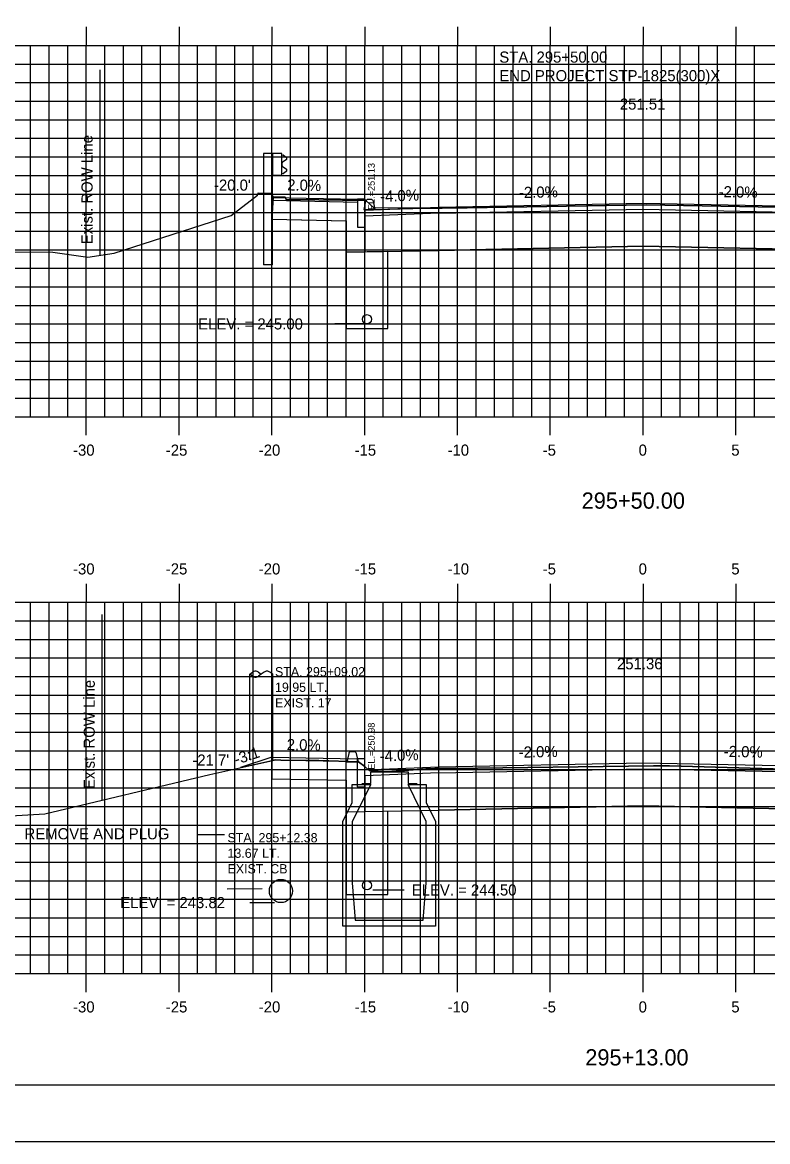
# Model space of a CAD drawing. Extents: x 859575 to 859745, y 366268 to 366378.
# Drawn here: x 859624.4 to 859664.5, y 366268.2 to 366328.5 of the extents above; entities that cross this region are included whole.
import ezdxf

# ---------------------------------------------------------------- set-up
doc = ezdxf.new("R2010")
doc.units = 0
for name, color, linetype in [('ANNOTATION', 7, 'Continuous'), ('BORDER', 7, 'Continuous'), ('D_Curb_Type_1_Lt', 7, 'Continuous'), ('D_Drainage_Culvert', 7, 'Continuous'), ('D_Roadway_Centerline_Text', 7, 'Continuous'), ('D_Roadway_Edge_Shoulder', 7, 'Continuous'), ('D_Roadway_FinishedGrade', 7, 'Continuous'), ('D_Roadway_Sidewalks_Paved', 7, 'Continuous'), ('D_Roadway_SubGrade', 7, 'Continuous'), ('D_Text_Monospaced', 7, 'Continuous'), ('D_Text_Standard', 7, 'Continuous'), ('E_ROW_Line', 7, 'Continuous'), ('H_V ANNOTATION', 7, 'Continuous'), ('JUNK COM EXC', 7, 'Continuous'), ('JUNK FILL', 7, 'Continuous'), ('junk strct exc', 7, 'Continuous'), ('MAJOR', 7, 'Continuous'), ('MINOR', 7, 'Continuous'), ('PDRAIN', 7, 'Continuous'), ('PLOT BOUNDARY', 7, 'Continuous'), ('S_Curb_Type_3', 7, 'Continuous'), ('S_Drainage_CB', 7, 'Continuous'), ('S_Guardrail_Beam', 7, 'Continuous'), ('S_Roadway_Centerline', 7, 'Continuous'), ('S_Utilities_Pole_Power', 7, 'Continuous')]:
    doc.layers.add(name, color=color, linetype=linetype)

msp = doc.modelspace()

# ---------------------------------------------------------------- linework, layer by layer
at = {"layer": 'ANNOTATION'}
for p, q in [((859633.835, 366284.72), (859635.248, 366284.72)), ((859637.266, 366281.799), (859635.393, 366281.786))]:
    msp.add_line(p, q, dxfattribs=at)
at = {"layer": 'BORDER'}
msp.add_line((859582.797, 366271.236), (859742.797, 366271.236), dxfattribs=at)
at = {"layer": 'D_Curb_Type_1_Lt'}
for points in [[(859642.408, 366318.954), (859642.408, 366317.454), (859642.824, 366317.454), (859642.824, 366318.954)], [(859642.385, 366288.799), (859642.385, 366287.299), (859642.801, 366287.299), (859642.801, 366288.799)]]:
    msp.add_lwpolyline(points, close=True, dxfattribs=at)
at = {"layer": 'D_Drainage_Culvert'}
msp.add_circle((859638.286, 366281.681), 0.625, dxfattribs=at)
at = {"layer": 'D_Roadway_Edge_Shoulder'}
for points in [[(859642.824, 366318.371), (859646.797, 366318.53), (859657.797, 366318.75), (859668.797, 366318.53), (859671.791, 366318.41)], [(859642.797, 366288.215), (859646.797, 366288.375), (859657.797, 366288.595), (859668.797, 366288.375), (859672.789, 366288.216)]]:
    msp.add_lwpolyline(points, dxfattribs=at)
at = {"layer": 'D_Roadway_FinishedGrade'}
msp.add_lwpolyline([(859637.796, 366288.891), (859636.109, 366288.328)], dxfattribs=at)
at = {"layer": 'D_Roadway_Sidewalks_Paved'}
for points in [[(859637.819, 366319.045), (859642.408, 366318.954), (859642.408, 366318.787), (859637.819, 366318.879)], [(859637.796, 366288.891), (859642.385, 366288.799), (859642.385, 366288.632), (859637.796, 366288.724)]]:
    msp.add_lwpolyline(points, close=True, dxfattribs=at)
at = {"layer": 'D_Roadway_SubGrade'}
msp.add_line((859637.819, 366318.879), (859637.819, 366317.878), dxfattribs=at)
for points in [[(859637.819, 366317.878), (859641.801, 366317.798), (859641.797, 366316.097), (859642.797, 366316.117)], [(859668.239, 366316.208), (859657.797, 366316.417), (859646.797, 366316.197), (859646.797, 366318.197), (859657.797, 366318.417), (859668.239, 366318.208)], [(859637.796, 366288.724), (859637.796, 366287.724), (859641.801, 366287.644), (859641.797, 366285.942), (859642.797, 366285.962)]]:
    msp.add_lwpolyline(points, dxfattribs=at)
for points in [[(859646.797, 366318.197), (859642.797, 366318.037), (859642.797, 366316.117), (859646.797, 366316.197)], [(859646.797, 366288.042), (859642.797, 366287.882), (859642.797, 366285.962), (859646.797, 366286.042)], [(859646.797, 366286.042), (859646.797, 366288.042), (859657.797, 366288.262), (859668.797, 366288.042), (859668.797, 366286.042), (859657.797, 366286.262)]]:
    msp.add_lwpolyline(points, close=True, dxfattribs=at)
at = {"layer": 'D_Text_Standard'}
for points in [[(859642.922, 366312.237), (859641.873, 366312.237), (859641.193, 366312.237)], [(859643.244, 366281.736), (859644.925, 366281.736)], [(859636.606, 366281.056), (859637.933, 366281.056)]]:
    msp.add_lwpolyline(points, dxfattribs=at)
at = {"layer": 'E_ROW_Line'}
for p, q in [((859628.54, 366315.931), (859628.54, 366325.931)), ((859628.656, 366286.572), (859628.656, 366296.572))]:
    msp.add_line(p, q, dxfattribs=at)
at = {"layer": 'JUNK COM EXC'}
for points in [[(859667.018, 366318.498), (859657.962, 366318.648), (859648.31, 366318.491), (859646.971, 366318.475), (859646.082, 366318.477), (859643.288, 366318.487), (859642.868, 366318.878), (859640.33, 366318.917), (859638.572, 366318.935), (859638.513, 366319.072), (859637.86, 366319.085), (859637.796, 366317.878), (859641.801, 366317.798), (859641.797, 366316.097), (859646.797, 366316.197), (859657.797, 366316.417), (859668.239, 366316.208)], [(859668.536, 366288.155), (859659.214, 366288.419), (859658.795, 366288.425), (859658.355, 366288.418), (859647.53, 366288.285), (859646.925, 366288.287), (859646.584, 366288.284), (859646.095, 366288.27), (859644.021, 366288.11), (859643.042, 366288.179), (859642.804, 366288.381), (859642.458, 366288.643), (859640.331, 366288.713), (859638.286, 366288.739), (859638.012, 366288.757), (859637.796, 366288.708)], [(859637.796, 366288.708), (859637.796, 366287.724), (859641.801, 366287.644), (859641.797, 366285.942), (859646.797, 366286.042), (859657.797, 366286.262), (859668.797, 366286.042)]]:
    msp.add_lwpolyline(points, dxfattribs=at)
at = {"layer": 'JUNK FILL'}
msp.add_lwpolyline([(859637.797, 366288.708), (859637.797, 366288.891), (859637.796, 366288.891), (859636.109, 366288.328)], close=True, dxfattribs=at)
at = {"layer": 'junk strct exc'}
msp.add_lwpolyline([(859641.797, 366316.097), (859641.797, 366311.986), (859644.047, 366311.986), (859644.047, 366316.142)], close=True, dxfattribs=at)
at = {"layer": 'MAJOR'}
for p, q in [((859627.797, 366328.238), (859627.797, 366327.236)), ((859632.797, 366328.238), (859632.797, 366327.236)), ((859637.797, 366328.238), (859637.797, 366327.236)), ((859642.797, 366328.238), (859642.797, 366327.236)), ((859647.797, 366328.238), (859647.797, 366327.236)), ((859652.797, 366328.238), (859652.797, 366327.236)), ((859657.797, 366328.238), (859657.797, 366327.236)), ((859662.797, 366328.238), (859662.797, 366327.236)), ((859587.797, 366327.236), (859727.797, 366327.236)), ((859587.797, 366327.236), (859727.797, 366327.236)), ((859627.797, 366307.236), (859627.797, 366327.236)), ((859632.797, 366307.236), (859632.797, 366327.236)), ((859637.797, 366307.236), (859637.797, 366327.236)), ((859642.797, 366307.236), (859642.797, 366327.236)), ((859647.797, 366307.236), (859647.797, 366327.236)), ((859652.797, 366307.236), (859652.797, 366327.236)), ((859657.797, 366307.236), (859657.797, 366327.236)), ((859662.797, 366307.236), (859662.797, 366327.236)), ((859587.797, 366322.236), (859727.797, 366322.236)), ((859587.797, 366317.236), (859727.797, 366317.236)), ((859587.797, 366312.236), (859727.797, 366312.236)), ((859587.797, 366307.236), (859727.797, 366307.236)), ((859587.797, 366307.236), (859727.797, 366307.236)), ((859627.797, 366306.234), (859627.797, 366307.236)), ((859632.797, 366306.234), (859632.797, 366307.236)), ((859637.797, 366306.234), (859637.797, 366307.236)), ((859642.797, 366306.234), (859642.797, 366307.236)), ((859647.797, 366306.234), (859647.797, 366307.236)), ((859652.797, 366306.234), (859652.797, 366307.236)), ((859657.797, 366306.234), (859657.797, 366307.236)), ((859662.797, 366306.234), (859662.797, 366307.236)), ((859627.797, 366298.238), (859627.797, 366297.236)), ((859632.797, 366298.238), (859632.797, 366297.236)), ((859637.797, 366298.238), (859637.797, 366297.236)), ((859642.797, 366298.238), (859642.797, 366297.236)), ((859647.797, 366298.238), (859647.797, 366297.236)), ((859652.797, 366298.238), (859652.797, 366297.236)), ((859657.797, 366298.238), (859657.797, 366297.236)), ((859662.797, 366298.238), (859662.797, 366297.236)), ((859587.797, 366297.236), (859727.797, 366297.236)), ((859587.797, 366297.236), (859727.797, 366297.236)), ((859627.797, 366277.236), (859627.797, 366297.236)), ((859632.797, 366277.236), (859632.797, 366297.236)), ((859637.797, 366277.236), (859637.797, 366297.236)), ((859642.797, 366277.236), (859642.797, 366297.236)), ((859647.797, 366277.236), (859647.797, 366297.236)), ((859652.797, 366277.236), (859652.797, 366297.236)), ((859657.797, 366277.236), (859657.797, 366297.236)), ((859662.797, 366277.236), (859662.797, 366297.236)), ((859587.797, 366292.236), (859727.797, 366292.236)), ((859587.797, 366287.236), (859727.797, 366287.236)), ((859587.797, 366282.236), (859727.797, 366282.236)), ((859587.797, 366277.236), (859727.797, 366277.236)), ((859587.797, 366277.236), (859727.797, 366277.236)), ((859627.797, 366276.234), (859627.797, 366277.236)), ((859632.797, 366276.234), (859632.797, 366277.236)), ((859637.797, 366276.234), (859637.797, 366277.236)), ((859642.797, 366276.234), (859642.797, 366277.236)), ((859647.797, 366276.234), (859647.797, 366277.236)), ((859652.797, 366276.234), (859652.797, 366277.236)), ((859657.797, 366276.234), (859657.797, 366277.236)), ((859662.797, 366276.234), (859662.797, 366277.236))]:
    msp.add_line(p, q, dxfattribs=at)
at = {"layer": 'MINOR'}
for p, q in [((859624.797, 366307.236), (859624.797, 366327.236)), ((859625.797, 366307.236), (859625.797, 366327.236)), ((859626.797, 366307.236), (859626.797, 366327.236)), ((859628.797, 366307.236), (859628.797, 366327.236)), ((859629.797, 366307.236), (859629.797, 366327.236)), ((859630.797, 366307.236), (859630.797, 366327.236)), ((859631.797, 366307.236), (859631.797, 366327.236)), ((859633.797, 366307.236), (859633.797, 366327.236)), ((859634.797, 366307.236), (859634.797, 366327.236)), ((859635.797, 366307.236), (859635.797, 366327.236)), ((859636.797, 366307.236), (859636.797, 366327.236)), ((859638.797, 366307.236), (859638.797, 366327.236)), ((859639.797, 366307.236), (859639.797, 366327.236)), ((859640.797, 366307.236), (859640.797, 366327.236)), ((859641.797, 366307.236), (859641.797, 366327.236)), ((859643.797, 366307.236), (859643.797, 366327.236)), ((859644.797, 366307.236), (859644.797, 366327.236)), ((859645.797, 366307.236), (859645.797, 366327.236)), ((859646.797, 366307.236), (859646.797, 366327.236)), ((859648.797, 366307.236), (859648.797, 366327.236)), ((859649.797, 366307.236), (859649.797, 366327.236)), ((859650.797, 366307.236), (859650.797, 366327.236)), ((859651.797, 366307.236), (859651.797, 366327.236)), ((859653.797, 366307.236), (859653.797, 366327.236)), ((859654.797, 366307.236), (859654.797, 366327.236)), ((859655.797, 366307.236), (859655.797, 366327.236)), ((859656.797, 366307.236), (859656.797, 366327.236)), ((859658.797, 366307.236), (859658.797, 366327.236)), ((859659.797, 366307.236), (859659.797, 366327.236)), ((859660.797, 366307.236), (859660.797, 366327.236)), ((859661.797, 366307.236), (859661.797, 366327.236)), ((859663.797, 366307.236), (859663.797, 366327.236)), ((859587.797, 366326.236), (859727.797, 366326.236)), ((859587.797, 366325.236), (859727.797, 366325.236)), ((859587.797, 366324.236), (859727.797, 366324.236)), ((859587.797, 366323.236), (859727.797, 366323.236)), ((859587.797, 366321.236), (859727.797, 366321.236)), ((859587.797, 366320.236), (859727.797, 366320.236)), ((859587.797, 366319.236), (859727.797, 366319.236)), ((859587.797, 366318.236), (859727.797, 366318.236)), ((859587.797, 366316.236), (859727.797, 366316.236)), ((859587.797, 366315.236), (859727.797, 366315.236)), ((859587.797, 366314.236), (859727.797, 366314.236)), ((859587.797, 366313.236), (859727.797, 366313.236)), ((859587.797, 366311.236), (859727.797, 366311.236)), ((859587.797, 366310.236), (859727.797, 366310.236)), ((859587.797, 366309.236), (859727.797, 366309.236)), ((859587.797, 366308.236), (859727.797, 366308.236)), ((859624.797, 366277.236), (859624.797, 366297.236)), ((859625.797, 366277.236), (859625.797, 366297.236)), ((859626.797, 366277.236), (859626.797, 366297.236)), ((859628.797, 366277.236), (859628.797, 366297.236)), ((859629.797, 366277.236), (859629.797, 366297.236)), ((859630.797, 366277.236), (859630.797, 366297.236)), ((859631.797, 366277.236), (859631.797, 366297.236)), ((859633.797, 366277.236), (859633.797, 366297.236)), ((859634.797, 366277.236), (859634.797, 366297.236)), ((859635.797, 366277.236), (859635.797, 366297.236)), ((859636.797, 366277.236), (859636.797, 366297.236)), ((859638.797, 366277.236), (859638.797, 366297.236)), ((859639.797, 366277.236), (859639.797, 366297.236)), ((859640.797, 366277.236), (859640.797, 366297.236)), ((859641.797, 366277.236), (859641.797, 366297.236)), ((859643.797, 366277.236), (859643.797, 366297.236)), ((859644.797, 366277.236), (859644.797, 366297.236)), ((859645.797, 366277.236), (859645.797, 366297.236)), ((859646.797, 366277.236), (859646.797, 366297.236)), ((859648.797, 366277.236), (859648.797, 366297.236)), ((859649.797, 366277.236), (859649.797, 366297.236)), ((859650.797, 366277.236), (859650.797, 366297.236)), ((859651.797, 366277.236), (859651.797, 366297.236)), ((859653.797, 366277.236), (859653.797, 366297.236)), ((859654.797, 366277.236), (859654.797, 366297.236)), ((859655.797, 366277.236), (859655.797, 366297.236)), ((859656.797, 366277.236), (859656.797, 366297.236)), ((859658.797, 366277.236), (859658.797, 366297.236)), ((859659.797, 366277.236), (859659.797, 366297.236)), ((859660.797, 366277.236), (859660.797, 366297.236)), ((859661.797, 366277.236), (859661.797, 366297.236)), ((859663.797, 366277.236), (859663.797, 366297.236)), ((859587.797, 366296.236), (859727.797, 366296.236)), ((859587.797, 366295.236), (859727.797, 366295.236)), ((859587.797, 366294.236), (859727.797, 366294.236)), ((859587.797, 366293.236), (859727.797, 366293.236)), ((859587.797, 366291.236), (859727.797, 366291.236)), ((859587.797, 366290.236), (859727.797, 366290.236)), ((859587.797, 366289.236), (859727.797, 366289.236)), ((859587.797, 366288.236), (859727.797, 366288.236)), ((859587.797, 366286.236), (859727.797, 366286.236)), ((859587.797, 366285.236), (859727.797, 366285.236)), ((859587.797, 366284.236), (859727.797, 366284.236)), ((859587.797, 366283.236), (859727.797, 366283.236)), ((859587.797, 366281.236), (859727.797, 366281.236)), ((859587.797, 366280.236), (859727.797, 366280.236)), ((859587.797, 366279.236), (859727.797, 366279.236)), ((859587.797, 366278.236), (859727.797, 366278.236))]:
    msp.add_line(p, q, dxfattribs=at)
at = {"layer": 'PDRAIN'}
for points in [[(859641.797, 366316.097), (859641.797, 366311.986), (859644.047, 366311.986), (859644.047, 366316.142)], [(859641.797, 366285.942), (859641.797, 366281.486), (859644.047, 366281.486), (859644.047, 366285.987)]]:
    msp.add_lwpolyline(points, dxfattribs=at)
for centre in [(859642.922, 366312.486), (859642.922, 366281.986)]:
    msp.add_circle(centre, 0.25, dxfattribs=at)
at = {"layer": 'PLOT BOUNDARY'}
msp.add_lwpolyline([(859574.704, 366268.177), (859744.704, 366268.177), (859744.704, 366378.177), (859574.704, 366378.177)], close=True, dxfattribs=at)
at = {"layer": 'S_Curb_Type_3'}
for points in [[(859642.847, 366318.843), (859642.744, 366318.399), (859643.369, 366318.399), (859643.266, 366318.843)], [(859643.144, 366318.94), (859642.968, 366318.94)], [(859641.935, 366289.088), (859641.833, 366288.643), (859642.458, 366288.643), (859642.355, 366289.088)], [(859642.233, 366289.185), (859642.057, 366289.185)]]:
    msp.add_lwpolyline(points, dxfattribs=at)
for centre, start, end in [((859642.968, 366318.815), 90, 167.00538), ((859643.144, 366318.815), 12.99462, 90), ((859642.057, 366289.06), 90, 167.00538), ((859642.233, 366289.06), 12.99462, 90)]:
    msp.add_arc(centre, 0.125, start, end, dxfattribs=at)
at = {"layer": 'S_Drainage_CB'}
for p, q in [((859642.114, 366286.444), (859642.114, 366287.428)), ((859642.114, 366287.428), (859643.131, 366287.428)), ((859643.131, 366287.428), (859642.114, 366285.426)), ((859645.132, 366287.428), (859646.117, 366287.428)), ((859646.117, 366285.426), (859645.132, 366287.428)), ((859646.117, 366287.428), (859646.117, 366286.444)), ((859641.622, 366285.426), (859642.114, 366286.444)), ((859646.117, 366286.444), (859646.609, 366285.426)), ((859641.622, 366279.783), (859641.622, 366285.426)), ((859642.114, 366285.426), (859642.114, 366282.113)), ((859646.117, 366282.113), (859646.117, 366285.426)), ((859646.609, 366285.426), (859646.609, 366279.783)), ((859642.114, 366282.113), (859642.278, 366280.112)), ((859645.953, 366280.112), (859646.117, 366282.113)), ((859642.278, 366280.112), (859645.953, 366280.112)), ((859646.609, 366279.783), (859641.622, 366279.783))]:
    msp.add_line(p, q, dxfattribs=at)
msp.add_lwpolyline([(859642.639, 366287.469), (859643.131, 366287.469), (859643.131, 366288.093), (859645.132, 366288.093), (859645.132, 366287.469), (859645.624, 366287.469)], dxfattribs=at)
at = {"layer": 'S_Guardrail_Beam'}
for p, q in [((859637.346, 366321.418), (859637.346, 366315.418)), ((859637.838, 366321.418), (859637.346, 366321.418)), ((859638.328, 366321.418), (859637.838, 366321.418)), ((859637.838, 366321.418), (859637.838, 366320.251)), ((859638.328, 366320.251), (859638.328, 366321.418)), ((859638.328, 366321.345), (859638.41, 366321.331)), ((859638.341, 366320.88), (859638.341, 366320.789)), ((859638.57, 366321.081), (859638.374, 366320.945)), ((859638.426, 366321.324), (859638.57, 366321.224)), ((859638.41, 366320.339), (859638.328, 366320.324)), ((859638.374, 366320.725), (859638.57, 366320.589)), ((859638.57, 366320.446), (859638.426, 366320.346)), ((859637.838, 366315.418), (859637.838, 366320.251)), ((859637.838, 366320.251), (859638.328, 366320.251)), ((859637.838, 366315.418), (859637.346, 366315.418))]:
    msp.add_line(p, q, dxfattribs=at)
for centre, major_axis, start_param, end_param in [((859638.42, 366320.88), (-0.0789, 0), 5.323254, 6.283185), ((859638.402, 366321.29), (0.0417, 0), 0.959931, 1.396263), ((859638.519, 366321.152), (0.0877, 0), 5.323254, 7.243116), ((859638.42, 366320.789), (-0.0789, 0), 6.283185, 7.243116), ((859638.402, 366320.38), (0.0417, 0), 4.886922, 5.323254), ((859638.519, 366320.517), (0.0877, 0), 5.323254, 7.243116)]:
    msp.add_ellipse(centre, major_axis=major_axis, ratio=0.995501, start_param=start_param, end_param=end_param, dxfattribs=at)
at = {"layer": 'S_Roadway_Centerline'}
for points in [[(859621.757, 366316.112), (859625.994, 366316.097), (859627.885, 366315.829), (859629.308, 366316.05), (859635.61, 366318.072), (859637.019, 366319.174), (859637.049, 366319.217), (859637.063, 366319.291), (859637.767, 366319.288), (859637.86, 366319.085), (859638.513, 366319.072), (859638.572, 366318.935), (859638.67, 366318.935), (859640.33, 366318.917), (859642.868, 366318.878), (859643.288, 366318.487), (859643.369, 366318.399), (859646.082, 366318.477), (859646.971, 366318.475), (859648.31, 366318.491), (859657.962, 366318.648), (859667.018, 366318.498)], [(859616.423, 366285.299), (859625.561, 366285.834), (859634.453, 366287.955), (859638.012, 366288.757), (859638.286, 366288.739), (859640.331, 366288.713), (859642.458, 366288.643), (859642.804, 366288.381), (859643.042, 366288.179), (859644.021, 366288.11), (859646.095, 366288.27), (859646.584, 366288.284), (859646.925, 366288.287), (859647.53, 366288.285), (859658.355, 366288.418), (859658.795, 366288.425), (859659.214, 366288.419), (859668.536, 366288.155)]]:
    msp.add_lwpolyline(points, dxfattribs=at)
at = {"layer": 'S_Utilities_Pole_Power'}
for p, q in [((859636.601, 366293.366), (859636.757, 366293.476)), ((859636.601, 366288.746), (859636.604, 366293.366)), ((859636.757, 366293.255), (859636.601, 366293.366)), ((859637.07, 366293.476), (859637.226, 366293.366)), ((859637.226, 366293.366), (859637.07, 366293.255)), ((859637.383, 366293.476), (859637.226, 366293.366)), ((859637.851, 366293.366), (859637.695, 366293.476)), ((859637.851, 366288.746), (859637.854, 366293.366))]:
    msp.add_line(p, q, dxfattribs=at)
for centre, start, end in [((859636.914, 366293.255), 90, 125.26439), ((859636.914, 366293.476), 234.73561, 270), ((859636.914, 366293.255), 54.73561, 90), ((859636.914, 366293.476), 270, 305.26439), ((859637.539, 366293.255), 90, 125.26439), ((859637.539, 366293.255), 54.73561, 90)]:
    msp.add_arc(centre, 0.271, start, end, dxfattribs=at)

# ---------------------------------------------------------------- texts
at = {"layer": 'ANNOTATION'}
for s, rotation, p in [('2.0%', 358.85424, (859638.617, 366319.43)), ('-2.0%', 1.14576, (859651.114, 366319.016)), ('-2.0%', 358.85424, (859661.861, 366319.069)), ('-4.0%', 2.29061, (859643.64, 366318.804)), ('2.0%', 358.85424, (859638.594, 366289.275)), ('-2.0%', 1.14576, (859651.1, 366288.862)), ('-2.0%', 358.85424, (859662.14, 366288.909)), ('-3:1', 18.43495, (859635.883, 366288.469)), ('-4.0%', 2.29061, (859643.617, 366288.649))]:
    msp.add_text(s, height=0.6, rotation=rotation, dxfattribs=at).set_placement(p)
at = {"layer": 'D_Roadway_Centerline_Text'}
for s, p in [('251.51', (859656.545, 366323.782)), ('251.36', (859656.39, 366293.627))]:
    msp.add_text(s, height=0.6, dxfattribs=at).set_placement(p)
at = {"layer": 'D_Text_Monospaced'}
for s, height, p in [('STA. 295+09.02', 0.49998, (859637.966, 366293.244)), ('19.95 LT.', 0.5, (859637.966, 366292.41)), ('EXIST. 17', 0.5, (859637.966, 366291.57)), ('STA. 295+12.38', 0.49998, (859635.407, 366284.302)), ('13.67 LT.', 0.5, (859635.407, 366283.468)), ('EXIST. CB', 0.5, (859635.407, 366282.628))]:
    msp.add_text(s, height=height, dxfattribs=at).set_placement(p)
at = {"layer": 'D_Text_Standard'}
for s, p in [('STA. 295+50.00', (859650.05, 366326.313)), ('END PROJECT STP-1825(300)X', (859650.05, 366325.313)), ("-20.0'", (859634.677, 366319.414)), ('ELEV. = 245.00', (859633.825, 366311.937)), ("-21.7'", (859633.512, 366288.437)), ('REMOVE AND PLUG', (859624.471, 366284.465)), ('ELEV. = 244.50', (859645.333, 366281.436)), ('ELEV. = 243.82', (859629.628, 366280.756))]:
    msp.add_text(s, height=0.6, dxfattribs=at).set_placement(p)
for s, p in [(' EL.=251.13', (859643.34, 366318.234)), (' EL.=250.98', (859643.34, 366288.08))]:
    msp.add_text(s, height=0.36848, rotation=90, dxfattribs=at).set_placement(p)
at = {"layer": 'E_ROW_Line'}
for p in [(859628.14, 366316.531), (859628.256, 366287.172)]:
    msp.add_text('Exist. ROW Line', height=0.6, rotation=90, dxfattribs=at).set_placement(p)
at = {"layer": 'H_V ANNOTATION'}
for s, height, p in [('-30', 0.6, (859627.085, 366305.136)), ('-25', 0.6, (859632.083, 366305.136)), ('-20', 0.6, (859637.091, 366305.136)), ('-15', 0.6, (859642.254, 366305.136)), ('-10', 0.6, (859647.262, 366305.136)), ('-5', 0.6, (859652.388, 366305.136)), ('0', 0.6, (859657.556, 366305.136)), ('5', 0.6, (859662.548, 366305.136)), ('295+50.00', 0.875, (859654.488, 366302.28)), ('-30', 0.6, (859627.085, 366298.736)), ('-25', 0.6, (859632.083, 366298.736)), ('-20', 0.6, (859637.091, 366298.736)), ('-15', 0.6, (859642.254, 366298.736)), ('-10', 0.6, (859647.262, 366298.736)), ('-5', 0.6, (859652.388, 366298.736)), ('0', 0.6, (859657.556, 366298.736)), ('5', 0.6, (859662.548, 366298.736)), ('-30', 0.6, (859627.085, 366275.136)), ('-25', 0.6, (859632.083, 366275.136)), ('-20', 0.6, (859637.091, 366275.136)), ('-15', 0.6, (859642.254, 366275.136)), ('-10', 0.6, (859647.262, 366275.136)), ('-5', 0.6, (859652.388, 366275.136)), ('0', 0.6, (859657.556, 366275.136)), ('5', 0.6, (859662.548, 366275.136)), ('295+13.00', 0.875, (859654.684, 366272.28))]:
    msp.add_text(s, height=height, dxfattribs=at).set_placement(p)
at = {"layer": 'S_Roadway_Centerline'}
for s, p in [('C', (859657.957, 366318.648)), ('L', (859657.962, 366318.64)), ('C', (859658.79, 366288.425)), ('L', (859658.795, 366288.418))]:
    msp.add_text(s, height=0.0146, dxfattribs=at).set_placement(p)

doc.saveas('drawing.dxf')
